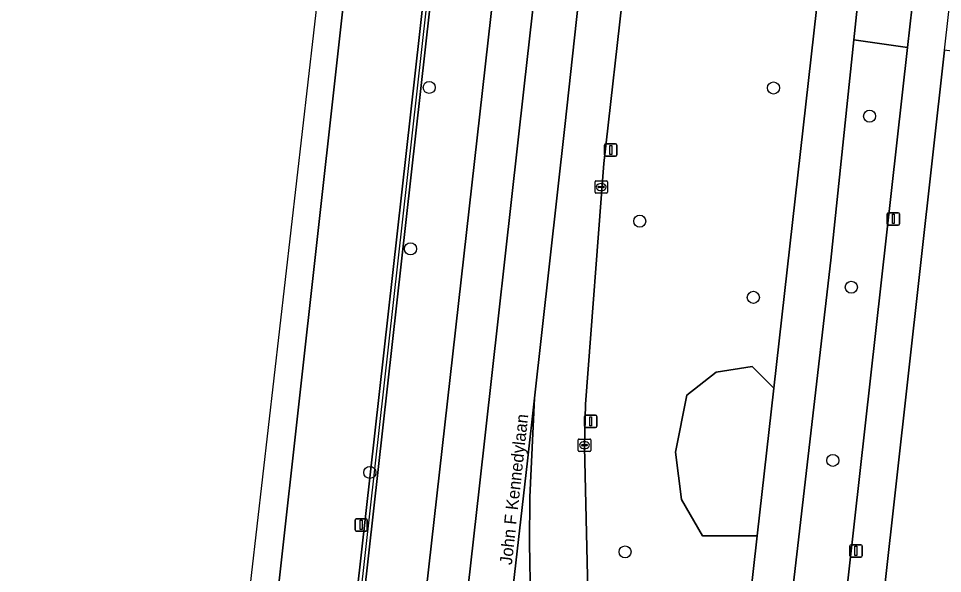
# Model space of a CAD drawing. Extents: x 162026 to 163502, y 387295 to 388169.
# Drawn here: x 162028.1 to 162102.9, y 387616.5 to 387661.5 of the extents above; entities that cross this region are included whole.
import ezdxf

# ---------------------------------------------------------------- set-up
doc = ezdxf.new("R2010")
doc.units = 0
for name, color, linetype in [('IMGEO_Berm_groen', 7, 'Continuous'), ('IMGEO_Boom', 7, 'Continuous'), ('IMGEO_Fietspad_gesloten', 7, 'Continuous'), ('IMGEO_Groenvoorziening', 7, 'Continuous'), ('IMGEO_Haag', 7, 'Continuous'), ('IMGEO_Hek', 7, 'Continuous'), ('IMGEO_Kolk', 7, 'Continuous'), ('IMGEO_Lichtmast', 7, 'Continuous'), ('IMGEO_Loofbos', 7, 'Continuous'), ('IMGEO_Openbare_ruimte_label', 7, 'Continuous'), ('IMGEO_Rijbaan_regionaal_gesloten', 7, 'Continuous'), ('IMGEO_Voetpad_open', 7, 'Continuous')]:
    doc.layers.add(name, color=color, linetype=linetype)

msp = doc.modelspace()

# ---------------------------------------------------------------- linework, layer by layer
at = {"layer": 'IMGEO_Berm_groen'}
msp.add_lwpolyline([(162070.558, 387750.033), (162070.715, 387751.433), (162082.73, 387858.959), (162085.888, 387887.498), (162092.582, 387948.213), (162098.331, 388000.033), (162100.436, 388019.009), (162101.034, 388018.962), (162098.927, 387999.967), (162093.178, 387948.147), (162086.483, 387887.426), (162083.326, 387858.893), (162071.311, 387751.367), (162071.154, 387749.967), (162064.775, 387692.973), (162048.017, 387543.217), (162038.634, 387465.803), (162038.336, 387465.839), (162038.038, 387465.875), (162047.421, 387543.289), (162064.177, 387693.016)], close=True, dxfattribs=at)
for points in [[(162064.05, 387750), (162057.767, 387693.483), (162056.727, 387684.126), (162047.718, 387603.08), (162036.137, 387500), (162030.941, 387454.36), (162030.73, 387452.526), (162030.286, 387448.671), (162029.893, 387445.259), (162029.553, 387442.306), (162029.44, 387441.239), (162028.358, 387431), (162028.258, 387430.068), (162028.052, 387428.264), (162033.041, 387427.758), (162033.149, 387428.806), (162035.199, 387428.61), (162035.081, 387427.551), (162037.244, 387427.331)], [(162037.244, 387427.331), (162040.156, 387427.036), (162040.402, 387429.193), (162040.503, 387430.114), (162041.617, 387440.377), (162041.731, 387441.427), (162042.071, 387444.383), (162042.463, 387447.798), (162042.907, 387451.657), (162043.118, 387453.488), (162048.26, 387500), (162059.518, 387601.502), (162069.77, 387692.609), (162071.42, 387707.267), (162076.229, 387750)], [(162097.909, 387681.02), (162095.684, 387659.769), (162100.033, 387659.157), (162102.473, 387680.926)], [(162100.033, 387659.157), (162095.684, 387659.769), (162093.817, 387641.924), (162088.785, 387598.25), (162087.719, 387589.002), (162086.365, 387577.251)], [(162085.955, 387558.431), (162086.662, 387549.732), (162089.38, 387549.805), (162089.039, 387552.072), (162088.912, 387553.622), (162088.832, 387557.702), (162089.116, 387561.772), (162091.906, 387586.663), (162093.16, 387597.85), (162100.033, 387659.157)]]:
    msp.add_lwpolyline(points, dxfattribs=at)
at = {"layer": 'IMGEO_Boom'}
for centre in [(162061.308, 387655.909), (162089.173, 387655.864), (162096.959, 387653.579), (162078.347, 387645.078), (162059.791, 387642.832), (162095.478, 387639.723), (162087.546, 387638.902), (162093.985, 387625.696), (162056.5, 387624.72), (162077.16, 387618.281)]:
    msp.add_circle(centre, 0.489, dxfattribs=at)
at = {"layer": 'IMGEO_Fietspad_gesloten'}
for points in [[(162093.817, 387641.924), (162095.684, 387659.769), (162097.909, 387681.02), (162098.729, 387688.74), (162098.791, 387689.232), (162095.805, 387689.61), (162093.527, 387669.911), (162089.208, 387631.54), (162087.862, 387619.58), (162086.291, 387605.618), (162083.789, 387583.725), (162083.056, 387577.239)], [(162086.365, 387577.251), (162087.719, 387589.002), (162088.785, 387598.25), (162093.817, 387641.924)]]:
    msp.add_lwpolyline(points, dxfattribs=at)
at = {"layer": 'IMGEO_Groenvoorziening'}
for points in [[(162064.775, 387692.973), (162071.154, 387749.967), (162071.311, 387751.367), (162083.326, 387858.893), (162086.483, 387887.426), (162093.178, 387948.147), (162098.927, 387999.967), (162101.034, 388018.962), (162100.436, 388019.009), (162098.331, 388000.033), (162092.582, 387948.213), (162085.888, 387887.498), (162082.73, 387858.959), (162070.715, 387751.433), (162070.558, 387750.033), (162064.177, 387693.016), (162047.421, 387543.289), (162038.038, 387465.875), (162038.336, 387465.839), (162038.634, 387465.803), (162048.017, 387543.217)], [(162116.563, 387618.274), (162104.764, 387619.607), (162108.876, 387658.111), (162105.237, 387658.623), (162103.023, 387658.934), (162095.191, 387588.673), (162123.431, 387582.879), (162123.471, 387583.358), (162123.67, 387585.284), (162112.88, 387586.426)]]:
    msp.add_lwpolyline(points, close=True, dxfattribs=at)
for points in [[(162086.722, 387750), (162086.309, 387746.228), (162080.161, 387691.589), (162078.737, 387678.932), (162075.453, 387649.755), (162073.957, 387630.261), (162073.874, 387626.787), (162074.15, 387615.148), (162079.544, 387500), (162080.248, 387483.154), (162080.393, 387480.335)], [(162081.286, 387480.096), (162086.919, 387488.185), (162085.969, 387500.662), (162081.962, 387553.202), (162081.287, 387569.524), (162082.706, 387583.685), (162083.789, 387583.725), (162086.291, 387605.618), (162087.862, 387619.58), (162083.423, 387619.58), (162081.742, 387622.534), (162081.242, 387626.351), (162082.151, 387630.987), (162084.533, 387632.853), (162087.441, 387633.308), (162089.208, 387631.54), (162093.527, 387669.911)]]:
    msp.add_lwpolyline(points, dxfattribs=at)
at = {"layer": 'IMGEO_Haag'}
msp.add_lwpolyline([(162064.775, 387692.973), (162071.154, 387749.967), (162071.311, 387751.367), (162083.326, 387858.893), (162086.483, 387887.426), (162093.178, 387948.147), (162098.927, 387999.967), (162101.034, 388018.962), (162100.436, 388019.009), (162098.331, 388000.033), (162092.582, 387948.213), (162085.888, 387887.498), (162082.73, 387858.959), (162070.715, 387751.433), (162070.558, 387750.033), (162064.177, 387693.016), (162047.421, 387543.289), (162038.038, 387465.875), (162038.336, 387465.839), (162038.634, 387465.803), (162048.017, 387543.217)], close=True, dxfattribs=at)
at = {"layer": 'IMGEO_Hek'}
msp.add_lwpolyline([(162064.476, 387692.994), (162047.719, 387543.253)], dxfattribs=at)
at = {"layer": 'IMGEO_Kolk'}
for p, q in [((162074.728, 387647.411), (162074.728, 387648.263)), ((162074.803, 387648.337), (162075.655, 387648.337)), ((162074.987, 387647.831), (162074.987, 387647.843)), ((162075.425, 387647.794), (162075.027, 387647.794)), ((162075.03, 387647.88), (162075.428, 387647.88)), ((162075.216, 387648.117), (162075.241, 387648.117)), ((162075.471, 387647.843), (162075.471, 387647.831)), ((162075.729, 387648.263), (162075.729, 387647.411)), ((162075.655, 387647.337), (162074.803, 387647.337)), ((162075.239, 387647.557), (162075.214, 387647.557)), ((162073.376, 387626.501), (162073.376, 387627.353)), ((162073.451, 387627.427), (162074.303, 387627.427)), ((162073.635, 387626.921), (162073.635, 387626.933)), ((162074.073, 387626.884), (162073.675, 387626.884)), ((162073.678, 387626.97), (162074.076, 387626.97)), ((162073.864, 387627.207), (162073.889, 387627.207)), ((162074.119, 387626.933), (162074.119, 387626.921)), ((162074.377, 387627.353), (162074.377, 387626.501)), ((162074.303, 387626.427), (162073.451, 387626.427)), ((162073.887, 387626.647), (162073.862, 387626.647))]:
    msp.add_line(p, q, dxfattribs=at)
for points in [[(162074.728, 387647.411), (162074.728, 387648.263)], [(162074.803, 387648.337), (162075.655, 387648.337)], [(162075.729, 387648.263), (162075.729, 387647.411)], [(162075.655, 387647.337), (162074.803, 387647.337)], [(162073.376, 387626.501), (162073.376, 387627.353)], [(162073.451, 387627.427), (162074.303, 387627.427)], [(162074.377, 387627.353), (162074.377, 387626.501)], [(162074.303, 387626.427), (162073.451, 387626.427)]]:
    msp.add_lwpolyline(points, dxfattribs=at)
for centre, radius, start, end in [((162074.805, 387648.261), 0.0765, 91.55205, 178.44795), ((162074.805, 387648.261), 0.0765, 91.55205, 178.44795), ((162075.027, 387647.84), 0.0403, 85.87752, 175.75265), ((162075.024, 387647.83), 0.0366, 178.93798, 274.71019), ((162075.428, 387647.837), 0.043, 264.86636, 352.45326), ((162075.432, 387647.842), 0.0386, 1.73085, 96.63898), ((162075.653, 387648.261), 0.0765, 1.55205, 88.44795), ((162075.653, 387648.261), 0.0765, 1.55205, 88.44795), ((162074.805, 387647.413), 0.0765, 181.55205, 268.44795), ((162074.805, 387647.413), 0.0765, 181.55205, 268.44795), ((162075.653, 387647.413), 0.0765, 271.55205, 358.44795), ((162075.653, 387647.413), 0.0765, 271.55205, 358.44795), ((162073.453, 387627.351), 0.0765, 91.55205, 178.44795), ((162073.453, 387627.351), 0.0765, 91.55205, 178.44795), ((162073.675, 387626.93), 0.0403, 85.87752, 175.75265), ((162073.672, 387626.92), 0.0366, 178.93798, 274.71019), ((162074.076, 387626.927), 0.043, 264.86636, 352.45326), ((162074.08, 387626.932), 0.0386, 1.73085, 96.63898), ((162074.301, 387627.351), 0.0765, 1.55205, 88.44795), ((162074.301, 387627.351), 0.0765, 1.55205, 88.44795), ((162073.453, 387626.503), 0.0765, 181.55205, 268.44795), ((162073.453, 387626.503), 0.0765, 181.55205, 268.44795), ((162074.301, 387626.503), 0.0765, 271.55205, 358.44795), ((162074.301, 387626.503), 0.0765, 271.55205, 358.44795)]:
    msp.add_arc(centre, radius, start, end, dxfattribs=at)
for centre, major_axis, ratio, start_param, end_param in [((162075.215, 387647.837), (-0.387, 0.002), 0.722429, 4.712389, 7.853982), ((162075.24, 387647.837), (-0.39, 0.002), 0.717154, 1.570796, 4.712389), ((162073.863, 387626.927), (-0.387, 0.002), 0.722429, 4.712389, 7.853982), ((162073.888, 387626.927), (-0.39, 0.002), 0.717154, 1.570796, 4.712389)]:
    msp.add_ellipse(centre, major_axis=major_axis, ratio=ratio, start_param=start_param, end_param=end_param, dxfattribs=at)
at = {"layer": 'IMGEO_Lichtmast'}
for p, q in [((162075.506, 387650.441), (162075.506, 387651.241)), ((162075.506, 387651.241), (162075.506, 387650.441)), ((162075.606, 387651.341), (162076.396, 387651.341)), ((162076.396, 387651.341), (162075.606, 387651.341)), ((162076.496, 387651.241), (162076.496, 387650.441)), ((162076.496, 387650.441), (162076.496, 387651.241)), ((162076.396, 387650.341), (162075.606, 387650.341)), ((162075.606, 387650.341), (162076.396, 387650.341)), ((162098.379, 387644.857), (162098.379, 387645.657)), ((162098.379, 387645.657), (162098.379, 387644.857)), ((162098.479, 387645.757), (162099.269, 387645.757)), ((162099.269, 387645.757), (162098.479, 387645.757)), ((162099.369, 387645.657), (162099.369, 387644.857)), ((162099.369, 387644.857), (162099.369, 387645.657)), ((162099.269, 387644.757), (162098.479, 387644.757)), ((162098.479, 387644.757), (162099.269, 387644.757)), ((162073.875, 387628.461), (162073.875, 387629.261)), ((162073.875, 387629.261), (162073.875, 387628.461)), ((162073.975, 387629.361), (162074.765, 387629.361)), ((162074.765, 387629.361), (162073.975, 387629.361)), ((162074.865, 387629.261), (162074.865, 387628.461)), ((162074.865, 387628.461), (162074.865, 387629.261)), ((162074.765, 387628.361), (162073.975, 387628.361)), ((162073.975, 387628.361), (162074.765, 387628.361)), ((162055.297, 387620.067), (162055.297, 387620.867)), ((162055.297, 387620.867), (162055.297, 387620.067)), ((162055.397, 387620.967), (162056.187, 387620.967)), ((162056.187, 387620.967), (162055.397, 387620.967)), ((162056.287, 387620.867), (162056.287, 387620.067)), ((162056.287, 387620.067), (162056.287, 387620.867)), ((162056.187, 387619.967), (162055.397, 387619.967)), ((162055.397, 387619.967), (162056.187, 387619.967)), ((162095.355, 387617.967), (162095.355, 387618.767)), ((162095.355, 387618.767), (162095.355, 387617.967)), ((162095.455, 387618.867), (162096.245, 387618.867)), ((162096.245, 387618.867), (162095.455, 387618.867)), ((162096.345, 387618.767), (162096.345, 387617.967)), ((162096.345, 387617.967), (162096.345, 387618.767)), ((162096.245, 387617.867), (162095.455, 387617.867)), ((162095.455, 387617.867), (162096.245, 387617.867))]:
    msp.add_line(p, q, dxfattribs=at)
for points in [[(162075.926, 387651.216), (162076.076, 387651.216), (162076.076, 387650.466), (162075.926, 387650.466), (162075.926, 387651.216)], [(162098.799, 387645.632), (162098.949, 387645.632), (162098.949, 387644.882), (162098.799, 387644.882), (162098.799, 387645.632)], [(162074.295, 387629.236), (162074.445, 387629.236), (162074.445, 387628.486), (162074.295, 387628.486), (162074.295, 387629.236)], [(162055.717, 387620.842), (162055.867, 387620.842), (162055.867, 387620.092), (162055.717, 387620.092), (162055.717, 387620.842)], [(162095.775, 387618.742), (162095.925, 387618.742), (162095.925, 387617.992), (162095.775, 387617.992), (162095.775, 387618.742)]]:
    msp.add_lwpolyline(points, dxfattribs=at)
for centre, start, end in [((162075.606, 387651.241), 90, 180), ((162075.606, 387651.241), 90, 180), ((162076.396, 387651.241), 0, 90), ((162076.396, 387651.241), 360, 90), ((162075.606, 387650.441), 180, 270), ((162075.606, 387650.441), 180, 270), ((162076.396, 387650.441), 270, 0), ((162076.396, 387650.441), 270, 0), ((162098.479, 387645.657), 90, 180), ((162098.479, 387645.657), 90, 180), ((162099.269, 387645.657), 0, 90), ((162099.269, 387645.657), 360, 90), ((162098.479, 387644.857), 180, 270), ((162098.479, 387644.857), 180, 270), ((162099.269, 387644.857), 270, 0), ((162099.269, 387644.857), 270, 0), ((162073.975, 387629.261), 90, 180), ((162073.975, 387629.261), 90, 180), ((162074.765, 387629.261), 0, 90), ((162074.765, 387629.261), 360, 90), ((162073.975, 387628.461), 180, 270), ((162073.975, 387628.461), 180, 270), ((162074.765, 387628.461), 270, 0), ((162074.765, 387628.461), 270, 0), ((162055.397, 387620.867), 90, 180), ((162055.397, 387620.867), 90, 180), ((162056.187, 387620.867), 0, 90), ((162056.187, 387620.867), 360, 90), ((162055.397, 387620.067), 180, 270), ((162055.397, 387620.067), 180, 270), ((162056.187, 387620.067), 270, 0), ((162056.187, 387620.067), 270, 0), ((162095.455, 387618.767), 90, 180), ((162095.455, 387618.767), 90, 180), ((162096.245, 387618.767), 0, 90), ((162096.245, 387618.767), 360, 90), ((162095.455, 387617.967), 180, 270), ((162095.455, 387617.967), 180, 270), ((162096.245, 387617.967), 270, 0), ((162096.245, 387617.967), 270, 0)]:
    msp.add_arc(centre, 0.1, start, end, dxfattribs=at)
at = {"layer": 'IMGEO_Loofbos'}
msp.add_lwpolyline([(162089.208, 387631.54), (162087.441, 387633.308), (162084.533, 387632.853), (162082.151, 387630.987), (162081.242, 387626.351), (162081.742, 387622.534), (162083.423, 387619.58), (162087.862, 387619.58)], close=True, dxfattribs=at)
at = {"layer": 'IMGEO_Rijbaan_regionaal_gesloten'}
for points in [[(162059.672, 387540.919), (162063.864, 387578.33), (162065.355, 387591.407), (162069.272, 387625.672), (162069.824, 387630.731), (162072.278, 387652.748), (162074.184, 387670.118), (162074.872, 387676.127), (162075.235, 387679.285), (162076.108, 387687.192), (162076.773, 387693.182), (162078.212, 387705.889), (162079.748, 387719.741), (162080.868, 387729.662), (162083.319, 387751.567)], [(162076.229, 387750), (162071.42, 387707.267), (162069.77, 387692.609), (162059.518, 387601.502), (162048.26, 387500), (162043.118, 387453.488), (162046.313, 387453.259), (162051.705, 387501.521), (162055.598, 387536.533), (162060.869, 387583.595), (162065.336, 387623.382), (162068.986, 387656.002), (162073.014, 387691.729), (162079.611, 387750.509)], [(162079.611, 387750.509), (162073.014, 387691.729), (162068.986, 387656.002), (162065.336, 387623.382), (162060.869, 387583.595), (162055.598, 387536.533)], [(162074.15, 387615.148), (162073.874, 387626.787), (162073.957, 387630.261), (162075.453, 387649.755), (162078.737, 387678.932), (162075.235, 387679.285), (162074.872, 387676.127), (162074.184, 387670.118), (162072.278, 387652.748), (162069.824, 387630.731), (162069.449, 387622.714), (162069.414, 387618.994), (162069.497, 387614.337), (162069.67, 387608.689), (162070.096, 387593.801), (162074.53, 387500), (162076.254, 387459.092), (162076.443, 387455.525), (162076.63, 387451.653), (162076.638, 387448.165), (162076.886, 387446.523)], [(162070.096, 387593.801), (162069.67, 387608.689), (162069.497, 387614.337), (162069.414, 387618.994), (162069.449, 387622.714), (162069.824, 387630.731), (162069.272, 387625.672), (162065.355, 387591.407), (162063.864, 387578.33), (162059.672, 387540.919), (162055.173, 387500.578), (162052.463, 387476.19), (162049.839, 387453.007), (162053.572, 387452.74), (162058.793, 387500), (162067.972, 387583.123)]]:
    msp.add_lwpolyline(points, dxfattribs=at)
msp.add_lwpolyline([(162028.947, 387454.503), (162030.941, 387454.36), (162036.137, 387500), (162047.718, 387603.08), (162056.727, 387684.126), (162054.699, 387684.33), (162043.666, 387588.407), (162041.014, 387565.347), (162039.989, 387556.439)], close=True, dxfattribs=at)
at = {"layer": 'IMGEO_Voetpad_open'}
for points in [[(162103.023, 387658.934), (162105.081, 387677.259), (162105.278, 387679.073), (162105.439, 387680.558), (162105.422, 387680.56), (162105.607, 387682.293), (162102.663, 387682.624), (162102.473, 387680.926), (162100.033, 387659.157), (162093.16, 387597.85), (162091.906, 387586.663), (162089.116, 387561.772), (162088.832, 387557.702), (162088.912, 387553.622)], [(162103.711, 387463.486), (162104.325, 387468.384), (162106.228, 387483.567), (162107.34, 387493.437), (162107.478, 387497.475), (162107.491, 387497.872), (162107.564, 387500), (162107.237, 387504.876), (162106.475, 387509.704), (162105.795, 387512.627), (162103.361, 387520.567), (162100.227, 387528.257), (162098.413, 387531.976), (162095.289, 387539.968), (162094.526, 387541.919), (162093.985, 387543.42), (162092.977, 387546.905), (162092.285, 387550.467), (162091.913, 387554.076), (162091.865, 387557.704), (162092.142, 387561.322), (162094.916, 387586.206), (162095.191, 387588.673), (162103.023, 387658.934)]]:
    msp.add_lwpolyline(points, dxfattribs=at)

# ---------------------------------------------------------------- texts
at = {"layer": 'IMGEO_Openbare_ruimte_label'}
msp.add_text('John F Kennedylaan', height=1, rotation=83.74207, dxfattribs=at).set_placement((162067.993, 387617.197))

doc.saveas('drawing.dxf')
